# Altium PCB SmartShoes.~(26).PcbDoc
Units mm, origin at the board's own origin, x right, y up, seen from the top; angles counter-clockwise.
Board outline 25 x 34 mm, 2 copper layers (Top Layer, Bottom Layer), stack 1.271 mm thick; 50 components, 38 nets, 203 pads, 291 vias.
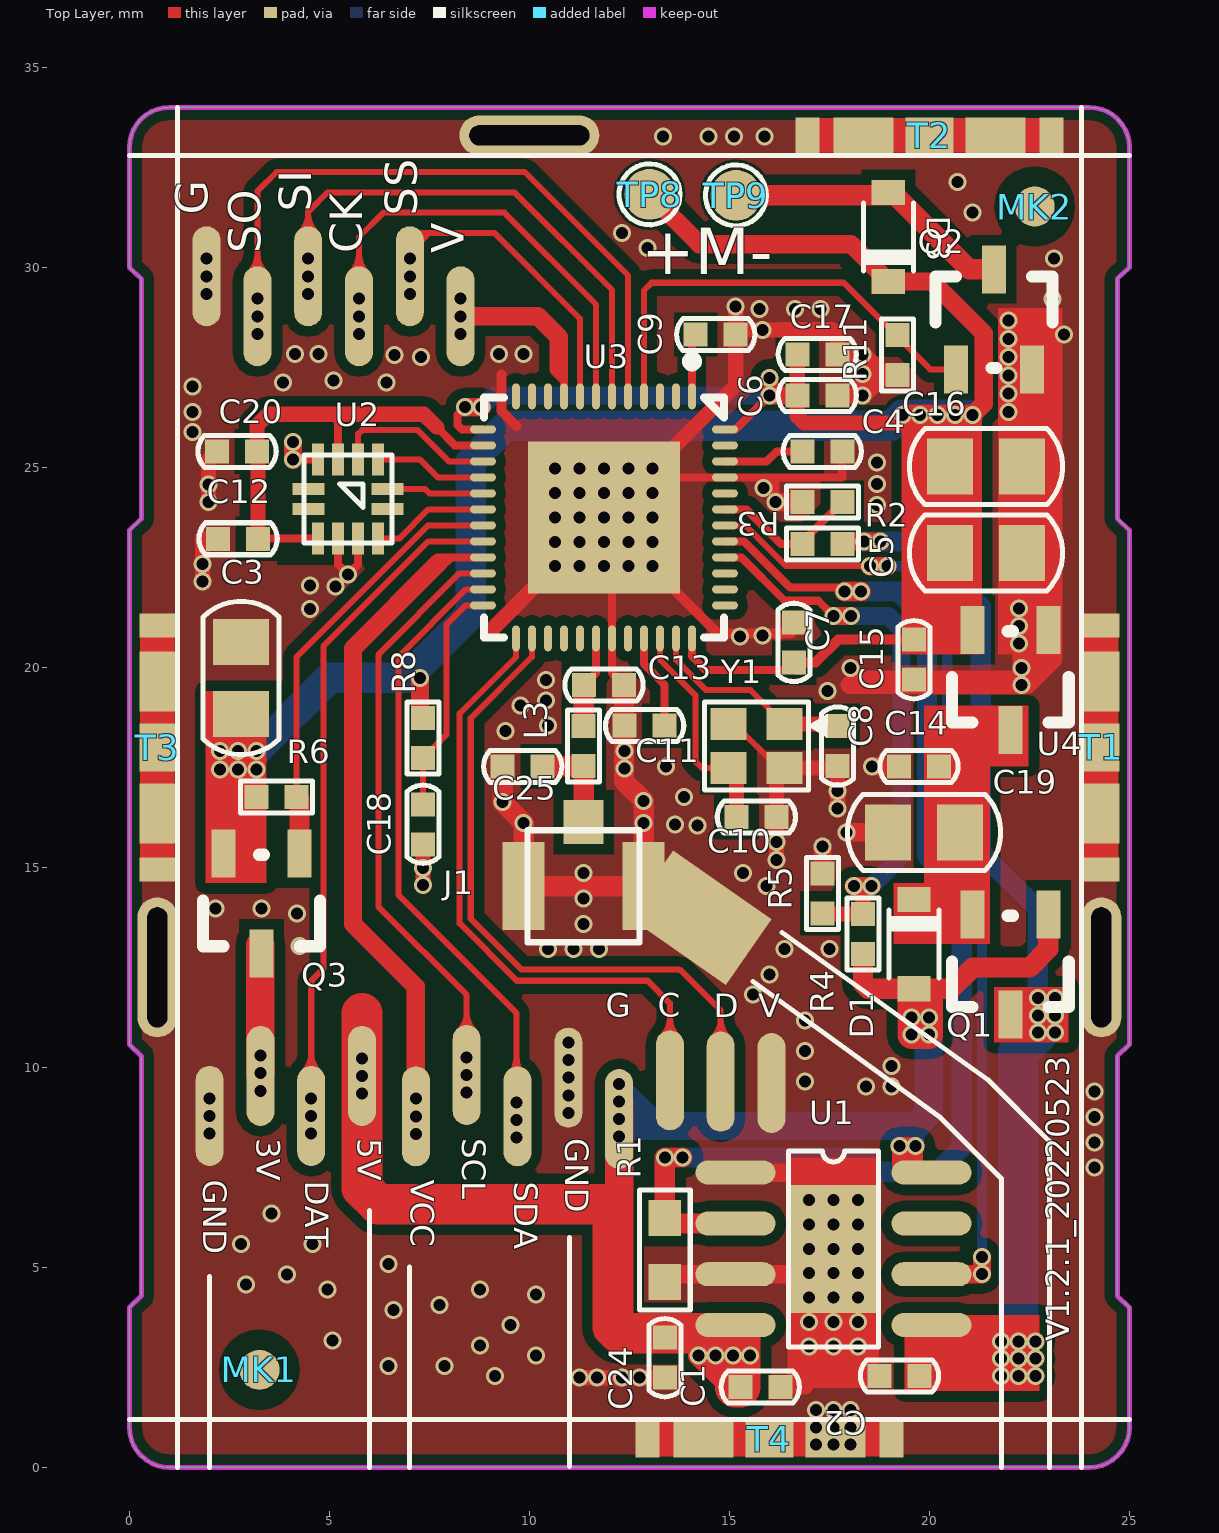
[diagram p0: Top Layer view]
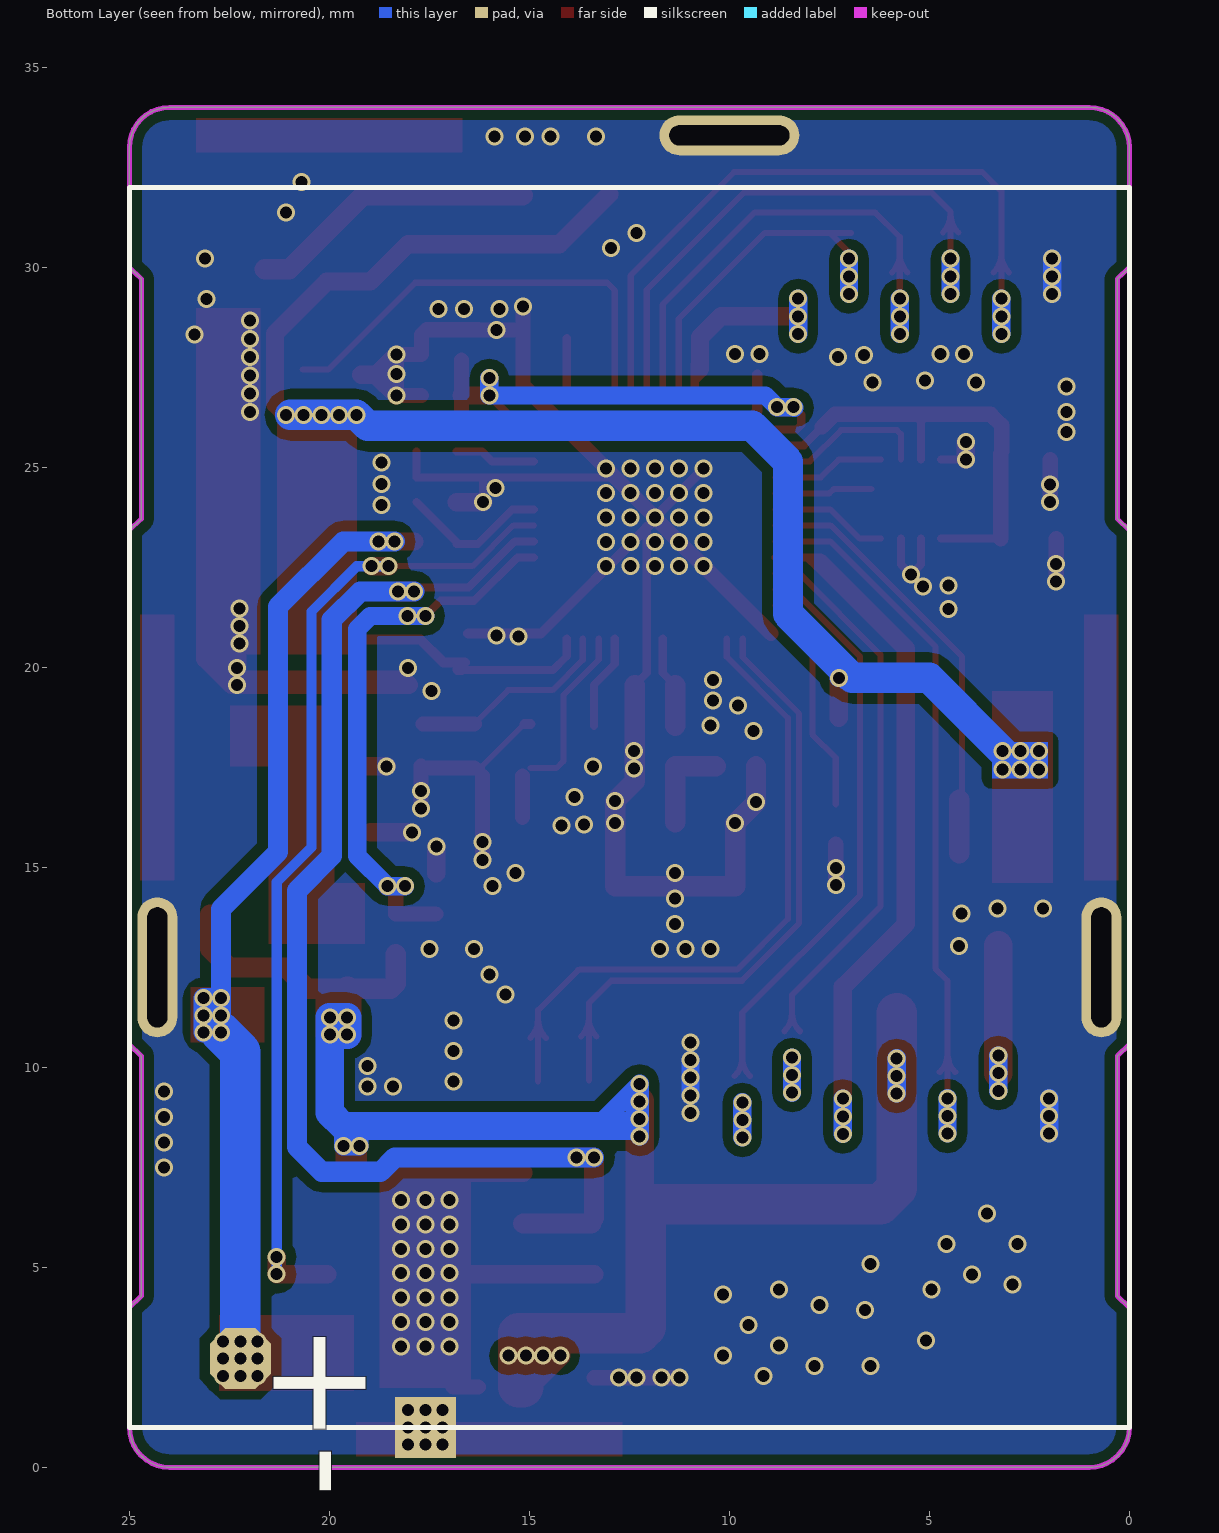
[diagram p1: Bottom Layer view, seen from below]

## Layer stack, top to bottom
Top Layer: signal copper 0.0356
Dielectric: core 1.2, FR-4, Dk 4.8
Bottom Layer: signal copper 0.0356

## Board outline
0,1 0,4 0.3,4.286 0.3,10.286 0,10.572 0,23.428 0.3,23.714 0.3,29.714 0,30 0,33 cw(c1,33) 1,34 24,34 cw(c24,33) 25,33 25,30 24.7,29.714 24.7,23.714 25,23.428 25,10.572 24.7,10.286 24.7,4.286 25,4 25,1 cw(c24,1) 24,0 1,0 cw(c1,1)

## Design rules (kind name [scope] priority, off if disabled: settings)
Clearance Clearance_1 [InPolygon] p1: gap=0.254
Clearance [All] p2: gap=0.127
ComponentClearance [All] p1 off: gap=0.254 collisioncheckmode=3 verticalgap=0.254 showdistances=FALSE
Height [All] p1 off: minheight=0 maxheight=25.4 prefheight=12.7
HoleSize [All] p1 off: absolutevalues=TRUE maxlimit=2.54 minlimit=0.025 maxpercent=80.000 minpercent=20.000
HoleToHoleClearance [All] p1 off: gap=0.254 allowstackedmicrovias=TRUE
LayerPairs [All] p1 off: enforce=TRUE
MinimumSolderMaskSliver [All] p1 off: minsoldermaskwidth=0.254
NetAntennae [All] p1 off: netantennaetolerance=0
PlaneClearance [All] p1: clearance=1
PlaneConnect [All] p1: planeconnectstyle=Direct reliefexpansion=0.508 reliefentries=4 reliefconductorwidth=0.254 reliefairgap=0.254
PolygonConnect PolygonConnect_1 [isVia] p1: connectstyle=Direct reliefconductorwidth=0.254 reliefentries=4 polygonreliefangle="90 Angle" airgapwidth=0.254
PolygonConnect [All] p2: connectstyle=Direct reliefconductorwidth=0.254 reliefentries=4 polygonreliefangle="90 Angle" airgapwidth=0.254
RoutingVias [All] p1: holewidth=0.305 width=0.559 viastyle="Through Hole" minholewidth=0.203 minwidth=0.356 maxholewidth=254 maxwidth=2539.975
SilkToSilkClearance [All] p1 off: silktosilkclearance=0.254
SilkscreenOverComponentPads [All] p1 off: minsilkscreentomaskgap=0.254
SolderMaskExpansion [All] p1: expansion=0.102
Width [All] p1: maxlimit=25.4 minlimit=0.127 preferedwidth=0.203
17 further rules are at their usual default settings.

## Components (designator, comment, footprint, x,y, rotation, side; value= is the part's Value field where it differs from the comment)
C1 "0.1uF" 0402C 15.773,2.01 r0 top
C2 "10uF" 0402C 19.253,2.289 r180 top
C3 "22uF" 0805C 2.794,19.736 r270 top
C4 "1uF" 0402C 17.323,25.4 r180 top
C5 "22uF" 0805C 21.412,22.86 r0 top
C6 "2.2uF" 0402C 17.199,26.797 r0 top
C7 "0.1uF" 0402C 16.612,20.625 r90 top
C8 "12pF" 0402C 17.707,18.034 r90 top
C9 "0.1uF" 0402C 14.659,28.321 r0 top
C10 "12pF" 0402C 15.675,16.256 r180 top
C11 "100pF" 0402C 12.881,18.542 r180 top
C12 "0.1uF" 0402C 2.718,23.216 r180 top
C13 "1.0pF" 0402C 11.865,19.558 r0 top
C14 "0.1uF" 0402C 19.739,17.526 r180 top
C15 "0.1uF" 0402C 19.612,20.193 r270 top
C16 "22uF" 0805C 21.412,25.019 r0 top
C17 "0.1uF" 0402C 17.199,27.824 r180 top
C18 "1uF" 0402C 7.341,16.078 r270 top
C19 "22uF" 0805C 19.866,15.875 r180 top
C20 "2.2uF" 0402C 2.692,25.4 r180 top
C24 "1uF" 0402C 13.386,2.743 r270 top
C25 "NC" 0402C 9.833,17.526 r180 top
D1 "SS14" SOD-323 19.612,13.081 r90 top
D3 "SS14" SOD-323 18.974,30.759 r270 top
J1 "ATN" IPX 11.357,16.129 r180 top
L3 "3.3nH" 0402L 11.357,18.034 r270 top
MK1 "TP" MARK 3.251,2.438 r0 top
MK2 "TP" MARK 22.631,31.521 r90 top
Q1 "AO3401" SOT-23-3 22.025,12.573 r180 top locked
Q2 "AO3400" SOT-23 21.615,28.702 r0 top
Q3 "AO3401" SOT-23-3 3.302,14.097 r180 top
R1 "3K/1%" 0603RM 13.386,5.436 r90 top
R2 "200K/1%" 0402R 17.323,23.089 r0 top
R3 "300K/1%" 0402R 17.323,24.13 r0 top
R4 "1K" 0402R 18.342,13.335 r90 top
R5 "10K" 0402R 17.326,14.351 r90 top
R6 "10K" 0402R 3.683,16.764 r180 top
R8 "10K" 0402R 7.341,18.237 r90 top
R11 "1K" 0402R 19.202,27.813 r90 top
T1 "铜柱D2*1.8" 屏蔽罩夹_1 24.3,18 r90 top
T2 "铜柱D2*1.8" 屏蔽罩夹_1 20,33.3 r180 top
T3 "铜柱D2*1.8" 屏蔽罩夹_1 0.7,18 r90 top
T4 "铜柱D2*1.8" 屏蔽罩夹_1 16,0.7 r180 top
TP8 "" testpoint 13.005,31.826 r0 top
TP9 "" testpoint 15.164,31.801 r0 top
U1 "TP4056X" SOP-8P 17.602,5.464 r0 top
U2 "QMA7981" LGA-12_2*2-e0.25 5.461,24.206 r270 top
U3 "NRF52832-QFAA-R" QFN48P-6X6 11.865,23.749 r270 top locked
U4 "XC6206P302MR" SOT-23 22.025,19.685 r180 top
Y1 "32MHz/12pF/10PPM" XTAL-SMD-2016 15.675,18.034 r180 top

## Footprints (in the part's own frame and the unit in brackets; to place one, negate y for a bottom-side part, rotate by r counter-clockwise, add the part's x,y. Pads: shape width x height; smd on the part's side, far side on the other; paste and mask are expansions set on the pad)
0402C [mm]
  rect 0.6x0.6 smd: 1(-0.5,0) 2(0.5,0)
  silkscreen extent -0.98,-0.4 0.98,0.4, body extent -0.5,-0.25 0.5,0.25, height 0.5
0402L [mm]
  rect 0.6x0.6 smd: 1(-0.5,0) 2(0.5,0)
  silkscreen extent -0.9,-0.4 0.9,0.4, body extent -0.5,-0.25 0.5,0.25, height 0.35
0402R [mm]
  rect 0.6x0.6 smd: 1(-0.5,0) 2(0.5,0)
  silkscreen extent -0.9,-0.4 0.9,0.4, body extent -0.5,-0.25 0.5,0.25, height 0.35
0603RM [mm]
  rect 0.9x0.813 smd: 1(-0.8,0) 2(0.8,0)
  silkscreen extent -1.5,-0.64 1.5,0.64, body extent -0.85,-0.4 0.85,0.4, height 0.56
0805C [mm]
  rect 1.15x1.4 smd: 1(-0.9,0) 2(0.9,0)
  silkscreen extent -1.91,-0.95 1.91,0.95, body extent -1,-0.6 1,0.6, height 1.2
IPX [mm]
  rect 1x1.1 smd: 1(0,0)
  rect 1.05x2.2 smd: 2(-1.5,1.6) 2(1.5,1.6)
  silkscreen extent -1.4,0.2 1.4,3, body extent -1.4,0.2 1.4,3, height 2
LGA-12_2*2-e0.25 [mm]
  rect 0.8x0.3 smd: 1(-0.987,0.75) 2(-0.987,0.25) 3(-0.987,-0.25) 4(-0.987,-0.75) 7(0.987,-0.75) 8(0.987,-0.25) 9(0.987,0.25) 10(0.987,0.75)
  rect 0.3x0.8 smd: 5(-0.25,-0.987) 6(0.25,-0.987) 11(0.25,0.987) 12(-0.25,0.987)
  silkscreen extent -1.1,-1.1 1.1,1.1
MARK [mm]
  round 1 smd mask+0.5: 1(0,0)
  Top Layer pour cut-out: -1,0 -0.924,-0.383 -0.707,-0.707 -0.383,-0.924 0,-1 0,-1 0.383,-0.924 0.707,-0.707 0.924,-0.383 1,0 1,0 0.924,0.383 0.707,0.707 0.383,0.924 0,1 0,1 -0.383,0.924 -0.707,0.707 -0.924,0.383 -1,0
QFN48P-6X6 [mm]
  oval 0.65x0.2 smd: 1(-3.025,2.2) 2(-3.025,1.8) 3(-3.025,1.4) 4(-3.025,1) 5(-3.025,0.6) 6(-3.025,0.2) 7(-3.025,-0.2) 8(-3.025,-0.6) 9(-3.025,-1) 10(-3.025,-1.4) 11(-3.025,-1.8) 12(-3.025,-2.2) 25(3.025,-2.2) 26(3.025,-1.8) 27(3.025,-1.4) 28(3.025,-1) 29(3.025,-0.6) 30(3.025,-0.2) 31(3.025,0.2) 32(3.025,0.6) 33(3.025,1) 34(3.025,1.4) 35(3.025,1.8) 36(3.025,2.2)
  oval 0.2x0.65 smd: 13(-2.2,-3.025) 14(-1.8,-3.025) 15(-1.4,-3.025) 16(-1,-3.025) 17(-0.6,-3.025) 18(-0.2,-3.025) 19(0.2,-3.025) 20(0.6,-3.025) 21(1,-3.025) 22(1.4,-3.025) 23(1.8,-3.025) 24(2.2,-3.025) 37(2.2,3.025) 38(1.8,3.025) 39(1.4,3.025) 40(1,3.025) 41(0.6,3.025) 42(0.2,3.025) 43(-0.2,3.025) 44(-0.6,3.025) 45(-1,3.025) 46(-1.4,3.025) 47(-1.8,3.025) 48(-2.2,3.025)
  rect 3.8x3.8 smd: P(0,0)
  silkscreen extent -4.02,-3 3,3, body extent -3,-3 3,3, height 0.9
SOD-323 [mm]
  rect 0.63x0.83 smd: 1(-1.115,0) 2(1.115,0)
  silkscreen extent -0.85,-0.63 0.85,0.63
SOP-8P [mm]
  oval 2x0.6 smd: 1(-2.45,1.905) 2(-2.45,0.635) 3(-2.45,-0.635) 4(-2.45,-1.905) 5(2.45,-1.905) 6(2.45,-0.635) 7(2.45,0.635) 8(2.45,1.905)
  rect 2.3x3.2 smd: P(0,0)
  silkscreen extent -1.13,-2.45 1.12,2.45, body extent -3,-2.45 3,2.45, height 1.7
SOT-23 [mm]
  rect 0.6x1.2 smd: 1(-0.95,-1.25) 2(0.95,-1.25) 3(0,1.25)
  silkscreen extent -1.46,-1.22 1.46,1.07, body extent -1.45,-1.4 1.45,1.4, height 1.2
SOT-23-3 [mm]
  rect 0.6x1.2 smd: 1(-0.95,-1.25) 2(0.95,-1.25) 3(0,1.25)
  silkscreen extent -1.46,-1.22 1.46,1.07, body extent -1.45,-1.4 1.45,1.4, height 1.2
testpoint [mm]
  round 1.27 smd: 1(0,0)
  silkscreen extent -0.76,-0.76 0.76,0.76
XTAL-SMD-2016 [mm]
  rect 0.9x0.8 smd: 1(-0.7,-0.55) 2(0.7,-0.55) 3(0.7,0.55) 4(-0.7,0.55)
  silkscreen extent -1.78,-1.1 1.3,1.1
屏蔽罩夹_1 [mm]
  rect 0.6x0.9 smd: 1(-3.05,0) 1(3.05,0)
  rect 1.5x0.9 smd: 1(-1.65,0) 1(1.65,0)
  rect 1.2x0.9 smd: 1(0,0)
  Top Layer region: -3.331,-0.432 3.324,-0.432 3.324,0.432 -3.331,0.432

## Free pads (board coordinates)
  oval 1x3.5 hole 0.5 slot 3 at 90 deg: 0(0.7,12.5) 0(24.3,12.5)
  oval 0.7x2.5 smd: 0(1.93,29.778) 0(2.007,8.787) 0(3.2,28.778) 0(3.277,9.787) 0(4.47,29.778) 0(4.547,8.787) 0(5.74,28.778) 0(5.817,9.787) 0(7.01,29.778) 0(7.163,8.776) 0(8.28,28.778) 0(8.433,9.809) 0(9.703,8.776) 0(10.973,9.743) 0(12.243,8.71) 0(13.513,9.677) 0(14.783,9.644) 0(16.053,9.611)
  oval 3.5x1 hole 0.5 slot 3 at 0 deg: 0(10,33.3)
  rect 2x3 smd rot 55: 0(14.249,13.741)
  oct 1.524x1.524 smd far side: 0(22.225,2.718)
  rect 1.524x1.524 smd far side: 1(17.602,1)

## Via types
v1: diameter 0.45, hole 0.3, Top Layer to Bottom Layer, tented both sides, 291 vias

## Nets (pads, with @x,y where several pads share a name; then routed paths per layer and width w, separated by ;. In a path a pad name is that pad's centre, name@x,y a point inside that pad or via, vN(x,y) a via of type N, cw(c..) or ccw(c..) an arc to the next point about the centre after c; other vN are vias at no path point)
+5V: C1.1 C24.1 D1.1 pad.0@5.817,9.787 pad.0@12.243,8.71 Q1.1 R4.1 U1.4 U1.8 | length 54.3
  Top Layer w0.381: v1(19.653,8.03) U1.8@19.653,7.63 ; U1.8 U1.8@19.653,7.369 ; U1.8@19.653,7.369 U1.8@19.653,7.63 ; U1.8@19.653,7.369 19.253,7.369 v1(19.253,8.03) U1.8@19.653,7.63
  Top Layer w0.457: v1(19.253,8.03) v1(19.653,8.03)
  Top Layer w0.508: C1.1@15.008,2.01 v1(14.224,2.794) v1(14.656,2.794) v1(15.088,2.794) 15.152,2.794 v1@15.273,2.794 ; R4.1 18.342,12.093 18.469,11.966 D1.1 20.551,11.966 21.082,12.497 22.504,12.497 22.975,12.967 Q1.1
  Top Layer w0.711: 12.243,6.325 v1(12.243,8.27) v1(12.243,8.71) v1(12.243,9.15) ; D1.1@19.558,11.912 v1(19.558,11.252) v1(19.558,10.82) v1(19.99,10.82) v1(19.99,11.252) ; 19.612,11.63 v1(19.99,11.252) ; D1.1@19.99,11.864 v1(19.99,11.252)
  Top Layer w1.016: 5.817,11.354 v1(5.817,10.227) v1(5.817,9.787) v1(5.817,9.347) 5.817,6.985 6.223,6.579 12.09,6.579 12.09,3.505 12.243,3.353 15.273,3.353 15.273,2.794 C1.1 ; C1.1@15.152,2.007 15.152,2.794 U1.4@15.152,3.302
  Bottom Layer w0.457: v1(5.817,9.347) v1(5.817,9.787) v1(5.817,10.227) ; v1(12.243,8.27) v1(12.243,8.71) v1(12.243,9.15) ; v1@12.395,8.997 v1(12.243,9.15) ; 13.298,8.534 v1(12.243,9.59) v1(12.243,9.15) ; 19.253,8.433 v1(19.253,8.03) v1(19.653,8.03) 19.653,8.527 19.66,8.534
  Bottom Layer w0.711: 12.395,8.534 13.298,8.534 19.66,8.534 19.99,8.865 v1(19.99,10.82) ; v1(19.99,10.82) v1(19.99,11.252) v1(19.558,11.252) v1(19.558,10.82) v1(19.99,10.82)
  other v1: 15.519,2.794
ACC_AD0: U2.1 U3.16 | length 2.8
  Top Layer w0.152: U2.1 7.268,25.193 7.712,24.749 U3.16
ACC_CSB: U2.10 U3.18 | length 2.9
  Top Layer w0.152: U2.10 6.746,23.219 7.476,23.949 U3.18
ACC_SCL: U2.12 U3.17 | length 2.4
  Top Layer w0.152: U2.12 7.395,24.456 7.503,24.349 U3.17
ACC_SDA: U2.2 U3.15 | length 4.1
  Top Layer w0.152: U2.2 5.711,25.828 5.817,25.933 7.205,25.933 7.99,25.149 U3.15
ACC_V: C12.1 C20.1 U2.3 U2.7 U3.14 | length 11.9
  Top Layer w0.203: C12.1@3.399,23.219 U2.7 ; U2.3 5.211,26.141 ; 7.683,26.012 8.131,25.564 8.131,25.549 U3.14 ; 5.211,26.141 5.063,26.289 5.359,26.289 5.211,26.141
  Top Layer w0.381: C20.1 3.192,26.052 3.467,26.327 7.368,26.327 7.683,26.012 ; C12.1 C20.1@3.218,25.349
ADC_BAT: R2.1 R3.2 U3.43 | length 3.7
  Top Layer w0.203: U3.43 15.429,23.949 16.29,23.089 R2.1 16.823,23.13 R3.2
ADC_CHARG: R1.2 U1.2 U3.41 | length 31.4
  Top Layer w0.203: U3.41 15.367,23.149 16.52,21.996 v1@18.012,21.996
  Top Layer w0.508: R1.2 v1(13.386,7.747) v1(13.826,7.747) ; R1.2@13.449,6.099 U1.2 ; v1(17.882,21.895) v1(18.288,21.895)
  Bottom Layer w0.508: v1(13.386,7.747) v1(13.826,7.747) 18.364,7.747 18.72,7.391 20.193,7.391 20.809,8.007 20.809,14.422 19.939,15.292 19.939,21.187 19.231,21.895 v1(18.288,21.895) v1(17.882,21.895)
ANT: C25.1 J1.1 L3.2 | length 2.4
  Top Layer w0.508: C25.1 L3.2@11.349,17.526 ; J1.1 L3.2
BAT+: C2.1 pad.0@22.225,2.718 Q1.3 R2.2 U1.5 | length 24.9
  Top Layer w0.457: R2.2@17.88,23.146 v1(18.367,23.146) v1(18.774,23.146)
  Bottom Layer w0.508: v1(18.367,23.146) v1(18.774,23.146) 19.653,23.146 21.285,21.514 21.285,15.383 22.711,13.957 v1(22.711,11.735) ; v1(22.711,10.871) v1(23.143,10.871) v1(23.143,11.303) v1(23.143,11.735) v1(22.711,11.735) ; v1(22.711,11.303) v1(22.711,11.735)
  Bottom Layer w1.016: pad.0@22.225,3.226 22.225,10.385 v1(22.711,10.871)
  other v1: 21.793,2.286 22.225,2.286 22.657,2.286 21.793,2.718 22.225,2.718 22.657,2.718 21.793,3.15 22.225,3.15 22.657,3.15
BAT_FULL: U1.6 U3.42 | length 25.3
  Top Layer w0.152: U3.42 15.398,23.549 16.417,22.53 v1(18.517,22.53)
  Top Layer w0.457: v1(18.517,22.53) v1(18.948,22.53) ; U1.6 v1(21.317,4.829) v1(21.317,5.261)
  Bottom Layer w0.254: v1@18.72,22.53 v1(18.948,22.53) 19.314,22.53 20.447,21.397 20.447,15.503 21.317,14.633 v1(21.317,5.261) v1(21.317,4.829)
CHG_ING: R4.2 R5.1 U3.40 | length 14.9
  Top Layer w0.203: U3.40 15.3,22.749 16.383,21.666 17.221,21.666 v1(17.602,21.285)
  Top Layer w0.381: R5.1@17.342,13.835 R4.2 v1@18.342,14.529
  Top Layer w0.457: v1(17.602,21.285) v1(18.042,21.285) ; v1(18.11,14.531) v1(18.55,14.531)
  Bottom Layer w0.457: v1(17.602,21.285) 18.978,21.285 19.304,20.96 19.304,15.285 v1(18.55,14.531) v1(18.11,14.531)
EX_B_POWER: pad.0@7.163,8.776 U3.21 | length 17.3
  Top Layer w0.203: 7.738,22.749 8.042,22.749 ; 7.798,22.504 8.042,22.749 ; U3.21 8.042,22.749
  Top Layer w0.457: v1(7.163,9.216) 7.163,12.014 5.588,13.589 5.588,20.472 7.735,22.619
  Bottom Layer w0.457: v1(7.163,8.336) v1(7.163,8.776) v1(7.163,9.216)
EX_B_SCL: pad.0@8.433,9.809 U3.22 | length 15.2
  Top Layer w0.152: pad.0@8.239,10.902 ccw(c7.772,11.37) 8.433,11.37 ; pad.0@8.626,10.902 cw(c9.094,11.37) 8.433,11.37 ; U3.22 8.252,22.349 6.223,20.32 6.223,14.021 8.433,11.811 8.433,11.37
  Bottom Layer w0.457: v1(8.433,9.369) v1(8.433,9.809) v1(8.433,10.249)
EX_B_SDA: pad.0@9.703,8.776 U3.23 | length 16
  Top Layer w0.152: U3.23 8.411,21.949 6.731,20.269 6.731,14.309 9.677,11.362 9.677,10.248 ; pad.0@9.484,9.78 ccw(c9.016,10.248) 9.677,10.248 ; pad.0@9.871,9.78 cw(c10.338,10.248) 9.677,10.248
  Bottom Layer w0.457: v1(9.677,8.247) v1(9.677,8.687) v1(9.677,9.127)
EX_F_MISO: pad.0@3.2,28.778 U3.5 | length 18.6
  Top Layer w0.152: pad.0@3.007,29.872 ccw(c2.539,30.339) 3.2,30.339 ccw(c3.861,30.339) pad.0@3.394,29.872 ; v1(3.2,28.778) 3.2,31.902 3.683,32.385 9.881,32.385 12.465,29.801 U3.5
  Bottom Layer w0.457: v1(3.2,28.338) v1(3.2,28.778) v1(3.2,29.218)
EX_F_MOSI: pad.0@4.47,29.778 U3.6 | length 15
  Top Layer w0.152: pad.0@4.277,30.872 ccw(c3.809,31.339) 4.47,31.339 ccw(c5.131,31.339) pad.0@4.664,30.872 ; v1(4.47,29.778) 4.47,31.394 4.953,31.877 9.627,31.877 12.065,29.439 U3.6
  Bottom Layer w0.457: v1(4.47,29.338) v1(4.47,29.778) v1(4.47,30.218)
EX_F_POWER: pad.0@8.28,28.778 U3.9 | length 5.4
  Top Layer w0.203: 10.693,27.33 10.865,27.159 ; U3.9 10.865,27.159 ; 10.865,27.568 10.865,27.159
  Top Layer w0.457: v1(8.28,28.778) 10.211,28.778 10.736,28.253 10.736,27.466
  Bottom Layer w0.457: v1(8.28,28.338) v1(8.28,28.778) v1(8.28,29.218)
EX_F_SCLK: pad.0@5.74,28.778 U3.7 | length 13.3
  Top Layer w0.152: pad.0@5.547,29.872 ccw(c5.079,30.339) 5.74,30.339 ccw(c6.401,30.339) pad.0@5.934,29.872 ; v1(5.74,28.778) 5.74,30.759 6.35,31.369 9.373,31.369 11.665,29.077 U3.7
  Bottom Layer w0.457: v1(5.74,28.338) v1(5.74,28.778) v1(5.74,29.218)
EX_F_SS: pad.0@7.01,29.778 U3.8 | length 9.3
  Top Layer w0.152: pad.0@6.96,30.861 7.493,30.861 ; v1(7.01,29.778) 7.01,30.378 7.493,30.861 ; U3.8 11.265,28.715 9.119,30.861 7.493,30.861
  Bottom Layer w0.457: v1(7.01,29.338) v1(7.01,29.778) v1(7.01,30.218)
GND: C1.2 C2.2 C3.1 C4.1 C5.2 C6.2 C7.2 C8.1 C9.2 C10.1 C11.2 C12.2 C13.2 C14.2 C15.2 C16.2 C17.1 C18.2 C19.2 C20.2 C24.2 C25.2 J1.2 pad.0@0.7,12.5 pad.0@1.93,29.778 pad.0@2.007,8.787 pad.0@10,33.3 pad.0@10.973,9.743 pad.0@14.249,13.741 pad.0@16.053,9.611 pad.0@24.3,12.5 pad.1 Q2.2 R1.1 R3.1 R5.2 R11.1 T1.1 T2.1 T3.1 T4.1 U1.1 U1.3 U1.P U2.4 U2.8 U2.9 U3.31 U3.45 U3.P U4.1 Y1.2 Y1.4 | length 88.3
  Top Layer w0.152: Y1.2@15.125,18.584 16.184,17.525 Y1.4@16.184,17.484
  Top Layer w0.203: v1(4.089,25.193) U2.4 ; v1(5.156,22.022) v1(5.461,22.327) ; U2.8 5.211,22.577 v1(5.461,22.327) ; U2.9 5.711,22.577 v1(5.461,22.327) ; U3.P@12.065,23.549 12.065,23.491 U3.31 12.065,19.858 C13.2 ; U3.P@12.865,24.749 U3.45 ; U3.45@14.895,24.744 U3.45 ; v1(16.154,24.13) 16.154,24.749 ; C4.1 17.823,24.749 16.154,24.749 ; U3.45 16.154,24.749
  Top Layer w0.254: 9.304,27.323 9.304,26.408 9.677,26.035 ; v1(10.646,24.968) v1(11.255,24.359) v1(11.865,23.749) 11.865,23.691 12.065,23.491 14.71,20.845 C7.2@16.539,20.845 ; Y1.2 Y1.2@15.125,18.584
  Top Layer w0.381: v1(1.829,22.149) v1(1.829,22.589) 1.829,23.216 ; v1(1.981,24.13) v1(1.981,24.57) C20.2@1.981,25.197 ; v1(7.341,14.554) C18.2 ; 8.96,20.844 v1(10.646,22.53) v1(11.255,23.139) v1(11.865,23.749) ; v1(11.252,2.243) v1(11.692,2.243) v1(12.319,2.243) v1(12.759,2.243) C24.2 ; U3.P@11.865,23.759 15.159,27.053 C9.2 ; v1(12.381,17.475) v1(12.381,17.915) C11.2 ; v1(15.159,29.027) C9.2 ; v1(16.175,15.189) v1(16.175,15.629) C10.1 Y1.4@16.175,17.284 ; C1.2 16.901,2.01 ; Y1.4 C8.1@17.657,17.484 ; C6.2 v1(18.326,26.797) v1(18.326,27.824) ; v1(17.707,16.467) v1(17.707,16.907) C8.1 ; v1(18.326,27.824) C17.1 17.699,28.313 17.571,28.441 16.267,28.441 16.261,28.435 v1(15.824,28.435) 15.273,28.435 C9.2
  Top Layer w0.457: v1(4.089,25.193) v1(4.089,25.629) ; R1.1@13.376,4.829 U1.3 U1.P@16.967,4.829 ; U1.1 16.869,7.369 ; v1(16.154,24.13) R3.1 ; R5.2 v1(17.326,15.523) ; v1(17.932,15.875) C19.2 ; v1(18.326,26.797) 18.842,27.313 ; v1(18.326,27.824) 18.837,27.313 18.842,27.313 ; v1(18.567,17.526) C14.2 ; R11.1 18.842,27.313 ; v1@22.169,19.693 C15.2 18.147,19.693 18.012,19.558 v1(22.304,19.558) ; v1@22.304,20.625 v1(22.304,19.99) ; U4.1@22.975,20.66 v1(22.304,19.99) ; U4.1@23.1,20.536 23.1,20.212 22.446,19.558 v1(22.304,19.558) ; v1(22.304,19.558) v1(22.304,19.99)
  Top Layer w0.508: C25.2 v1(9.333,16.629) v1(9.857,16.105) 9.857,14.529 12.857,14.529 v1(12.857,16.104) v1(12.857,16.661) 12.365,17.153 C13.2
  Bottom Layer w0.457: v1(1.93,29.338) v1(1.93,29.778) v1(1.93,30.218) ; v1(2.007,8.347) v1(2.007,8.787) v1(2.007,9.227) ; v1(10.973,9.303) v1(10.973,9.743) v1(10.973,10.183)
  other v1: 17.17,0.568 17.602,0.568 18.034,0.568 17.17,1 17.602,1 18.034,1 17.17,1.432 17.602,1.432 18.034,1.432 9.144,2.286 6.477,2.54 7.874,2.54 10.16,2.794 16.993,3.026 17.602,3.026 18.212,3.026 8.763,3.048 5.08,3.175 9.525,3.556 16.993,3.635 17.602,3.635 18.212,3.635 6.604,3.937 7.747,4.064 16.993,4.245 17.602,4.245 18.212,4.245 10.16,4.318 4.953,4.445 8.763,4.445 2.921,4.572 3.937,4.826 16.993,4.855 17.602,4.855 18.212,4.855 6.477,5.08 16.993,5.464 17.602,5.464 18.212,5.464 2.794,5.588 4.572,5.588 16.993,6.074 17.602,6.074 18.212,6.074 3.556,6.35 16.993,6.683 17.602,6.683 18.212,6.683 24.13,7.493 24.13,8.128 24.13,8.763 10.973,8.863 24.13,9.398 18.415,9.525 19.05,9.525 16.891,9.652 19.05,10.033 16.891,10.414 10.973,10.622 16.891,11.176 15.595,11.826 16.002,12.319 10.468,12.954 11.103,12.954 11.738,12.954 16.383,12.954 17.501,12.954 4.255,13.03 11.357,13.589 4.191,13.843 2.159,13.97 3.302,13.97 11.357,14.224 15.926,14.529 11.357,14.859 15.342,14.859 7.341,14.986 14.202,16.053 13.64,16.078 13.872,16.764 13.414,17.526 9.398,18.415 10.468,18.542 9.779,19.05 10.414,19.177 17.45,19.406 10.414,19.685 18.034,19.99 22.242,20.591 15.269,20.777 15.827,20.803 22.242,21.031 4.521,21.463 22.242,21.471 4.521,22.047 11.255,22.53 11.865,22.53 12.475,22.53 13.084,22.53 10.646,23.139 11.865,23.139 12.475,23.139 13.084,23.139 10.646,23.749 11.255,23.749 12.475,23.749 13.084,23.749 18.694,24.054 10.646,24.359 11.865,24.359 12.475,24.359 13.084,24.359 15.85,24.486 18.694,24.587 11.255,24.968 11.865,24.968 12.475,24.968 13.084,24.968 18.694,25.121 1.575,25.883 1.575,26.391 21.982,26.384 21.982,26.841 1.575,27.026 3.835,27.127 6.426,27.127 5.105,27.178 21.982,27.298 18.326,27.33 7.29,27.762 21.982,27.755 6.629,27.813 4.14,27.838 4.724,27.838 9.246,27.838 9.855,27.838 21.982,28.213 23.368,28.321 21.982,28.67 15.748,28.956 16.637,28.956 17.272,28.956 23.076,29.21 23.114,30.226 12.954,30.48 12.319,30.861 21.082,31.369 20.701,32.131 13.335,33.274 14.478,33.274 15.113,33.274 15.875,33.274
MT_EN: Q2.1 R11.2 U3.4 | length 11.4
  Top Layer w0.152: U3.4 12.865,29.426 13.056,29.616 17.856,29.616 20.021,27.452 Q2.1
MT_OUT: D3.1 Q2.3 TP9.1 | length 7.2
  Top Layer w0.508: TP9.1 19.152,31.801 21,29.952 Q2.3
NetC4_2: C4.2 U3.46 | length 2
  Top Layer w0.203: U3.46 15.932,25.149 16.183,25.4 C4.2
NetC8_2: C8.2 U3.35 Y1.1 | length 5.3
  Top Layer w0.152: U3.35 13.665,20.185 14.419,19.431 15.528,19.431 Y1.1 ; C8.2@17.657,18.584 C8.2
  Top Layer w0.381: Y1.1 C8.2@17.657,18.584
NetC9_1: C9.1 U3.1 | length 1.5
  Top Layer w0.203: U3.1 C9.1@14.065,28.227
NetC10_2: C10.2 U3.34 Y1.3 | length 5.4
  Top Layer w0.152: U3.34 13.265,20.19 14.151,19.304 14.151,17.653 14.32,17.484 Y1.3
  Top Layer w0.381: C10.2 Y1.3@15.175,17.284
NetC11_1: C11.1 U3.33 | length 2.4
  Top Layer w0.203: U3.33 12.865,20.082 13.381,19.566 C11.1
NetC13_1: C13.1 L3.1 U3.30 | length 2.3
  Top Layer w0.203: C13.1 11.665,19.858 U3.30
  Top Layer w0.508: L3.1 C13.1@11.357,19.55
RESET: C18.1 R8.1 U3.24 | length 5.8
  Top Layer w0.152: C18.1 R8.1 7.925,18.321 7.925,21.068 8.406,21.549 U3.24
RGB_DAT: pad.0@4.547,8.787 U3.20 | length 18.9
  Top Layer w0.152: pad.0@4.353,9.881 ccw(c3.886,10.348) 4.547,10.348 ccw(c5.208,10.348) pad.0@4.74,9.881 ; v1(4.547,8.787) v1(4.547,9.227) 4.547,12.167 4.851,12.471 4.851,20.523 7.477,23.149 U3.20
  Bottom Layer w0.457: v1(4.547,8.347) v1(4.547,8.787) v1(4.547,9.227)
RGB_EN: Q3.1 R6.1 U3.19 | length 11
  Top Layer w0.152: Q3.1@4.183,15.416 Q3.1 ; R6.1 4.183,20.261 7.471,23.549 U3.19
  Top Layer w0.508: Q3.1 R6.1@4.252,16.695
RX: U3.27
SWCLK: pad.0@13.513,9.677 U3.25 | length 16.8
  Top Layer w0.152: U3.25 9.665,20.257 8.255,18.847 8.255,13.6 9.689,12.167 12.954,12.167 13.513,11.608 pad.0@13.513,9.677 ; pad.0@13.319,10.77 ccw(c12.852,11.238) 13.513,11.238 ccw(c14.174,11.238) pad.0@13.706,10.77
SWDIO: pad.0@14.783,9.644 U3.26 | length 18.3
  Top Layer w0.152: U3.26 10.065,20.262 8.534,18.731 8.534,13.716 9.804,12.446 13.742,12.446 13.756,12.432 13.781,12.432 14.783,11.43 pad.0@14.783,10.084 ; pad.0@14.589,10.737 ccw(c14.122,11.205) 14.783,11.205 ccw(c15.444,11.205) pad.0@14.976,10.737 ; pad.0@14.783,9.644 pad.0@14.783,10.693
VBAT: C14.1 C19.1 D1.2 Q1.2 U4.3
VCC_NRF: C3.2 C5.1 C6.1 C7.1 C15.1 C16.1 C17.2 D3.2 Q3.2 R6.2 R8.2 TP8.1 U3.13 U3.36 U3.48 U4.2 | length 62.5
  Top Layer w0.203: v1(8.395,26.505) 8.204,26.314 8.204,26.06 8.316,25.949 U3.13 ; U3.36 14.065,20.279 14.405,19.939 C7.1@16.699,19.939 ; U3.48 15.154,25.949 v1(16.002,26.797)
  Top Layer w0.254: C7.1 17.153,20.125 17.721,20.693 C15.1 ; C7.1@16.699,19.939 C7.1@16.793,19.939
  Top Layer w0.381: C17.2@16.699,27.686 C6.1 16.699,26.281 16.869,26.111 20.704,26.111 20.871,25.944 C16.1@20.871,25.019
  Top Layer w0.457: R8.2@7.264,18.737 v1(7.264,19.736) ; v1(8.395,26.505) v1(8.808,26.505) ; TP8.1 14.249,30.582 18.037,30.582 D3.2 20.063,29.644 21.361,28.346 21.361,26.594 v1(21.082,26.314) ; v1(16.002,27.229) v1(16.002,26.797) C6.1
  Bottom Layer w0.457: 6.756,19.736 v1(7.264,19.736) ; v1@8.381,26.492 v1(8.395,26.505) v1(8.808,26.505) 9.1,26.797 v1(16.002,26.797) v1(16.002,27.229)
  Bottom Layer w0.762: v1(3.175,17.907) 5.004,19.736 6.934,19.736 8.534,21.336 8.534,25.146 9.423,26.035 19.043,26.035 v1(19.323,26.314) v1(19.763,26.314) v1(20.202,26.314) v1(20.642,26.314) v1@20.972,26.314
  other v1: 2.261,17.45 2.718,17.45 3.175,17.45 2.261,17.907 2.718,17.907
VCC_RGB: pad.0@3.277,9.787 Q3.3 | length 4.5
  Top Layer w0.152: v1(3.277,9.855) v1(3.277,10.295)
  Top Layer w0.711: v1(3.277,9.855) Q3.3@3.277,13.056
  Bottom Layer w0.457: v1(3.277,9.415) v1(3.277,9.855) v1(3.277,10.295)
pads on no net: MK1.1 MK2.1 U1.7 U2.5 U2.6 U2.11 U3.2 U3.3 U3.10 U3.11 U3.12 U3.28 U3.29 U3.32 U3.37 U3.38 U3.39 U3.44 U3.47

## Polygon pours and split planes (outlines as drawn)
GND on Bottom Layer "Bottom Layer-No Net" (solid, remove dead copper, pour order 4): 0,0 24,0 25,1 25,33 24,34 1,34 0,33
GND on Top Layer "Bottom Layer-No Net" (solid, remove dead copper, pour order 3): 0,0 24,0 25,1 25,33 24,34 1,34 0,33

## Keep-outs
Keep-Out Layer:
  the board outline again, w0.127

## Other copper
Top Layer:
  rectangle net VCC_NRF: 1.905,14.605 3.429,19.406
  region net GND: 18.745,1.984 18.745,7.75 16.459,7.75 16.459,1.984
  region net BAT+: 22.758,1.905 22.758,3.813 19.38,3.813 19.38,1.905
  rectangle net VBAT: 19.866,13.081 21.517,19.05
  rectangle net VBAT: 19.104,13.081 19.866,14.605
  rectangle net VBAT: 19.866,17.526 22.482,19.05
  rectangle net BAT+: 21.619,10.617 23.473,12.014
  rectangle net VCC_NRF: 19.304,20.32 21.311,26.568
  rectangle net GND: 21.717,20.32 23.328,28.981
  pour cut-out: 3.691,25.786 3.691,22.565 7.188,22.565 7.188,25.778
Bottom Layer:
  rectangle net VCC_NRF: 2.032,17.221 3.429,18.136

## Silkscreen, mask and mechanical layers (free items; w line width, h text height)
Top Overlay:
  lines w0.127: 0,1.2 25,1.2 ; 0,32.8 25,32.8 ; 1.2,0 1.2,34 ; 2,0 2,4.775 ; 6,0 6,6.426 ; 7,0 7,5.004 ; 11,0.025 11,5.74 ; 15.59,12.15 20.257,8.762 21.8,7.219 21.8,0 ; 16.314,13.371 21.457,9.698 23,8.155 23,0 ; 23.8,0 23.8,34
  text "SI" at 4.826,31.394 h1.4 r90
  text "G" at 2.235,31.318 h1.4 r90
  text "SS" at 7.468,31.293 h1.4 r90
  text "SO" at 3.556,30.353 h1.4 r90
  text "CK" at 6.096,30.353 h1.4 r90
  text "V" at 8.636,30.353 h1.4 r90
  text "+M-" at 12.802,29.439 h2
  text "G" at 11.913,11.06 h1.02
  text "C" at 13.208,11.06 h1.02
  text "D" at 14.605,11.049 h1.02
  text "V" at 15.723,11.049 h1.02
  text "3V" at 2.986,8.23 h1.02 r270
  text "5V" at 5.512,8.23 h1.02 r270
  text "SCL" at 8.124,8.23 h1.02 r270
  text "GND" at 10.693,8.23 h1.02 r270
  text "GND" at 1.651,7.188 h1.02 r270
  text "VCC" at 6.833,7.188 h1.02 r270
  text "DAT" at 4.191,7.163 h1.02 r270
  text "SDA" at 9.423,7.137 h1.02 r270
  text "V1.2.1_20220523" at 23.698,3.15 h1.02 r90
Bottom Overlay:
  lines w0.127: 0,1 0,32 25,32 25,1 0,1
  text "+-" at 18.212,3.635 h4.57 r270
Mechanical 15:
  lines w0.127: -0.559,0 0,0 0,-0.533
